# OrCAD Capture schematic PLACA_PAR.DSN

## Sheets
1 PAGE2: size A
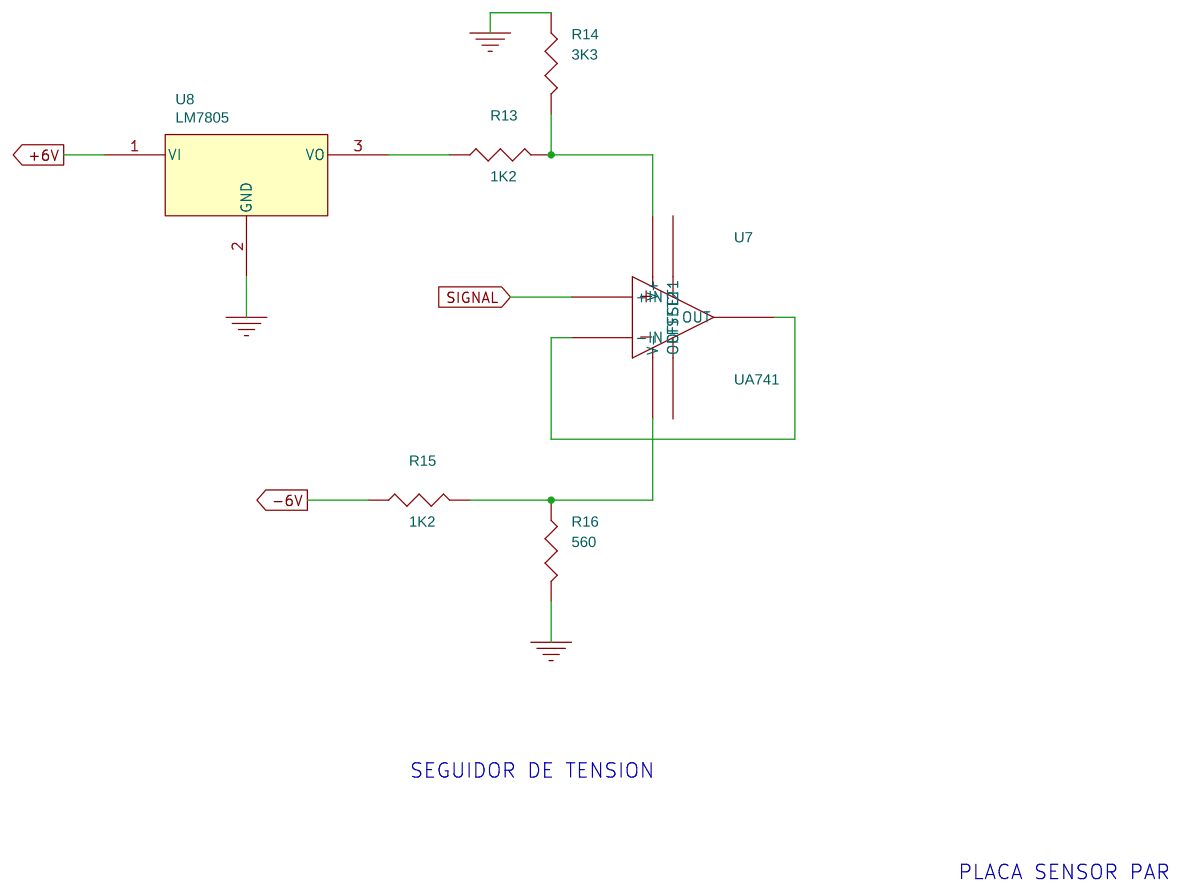
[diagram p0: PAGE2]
2 PAGE1: size A
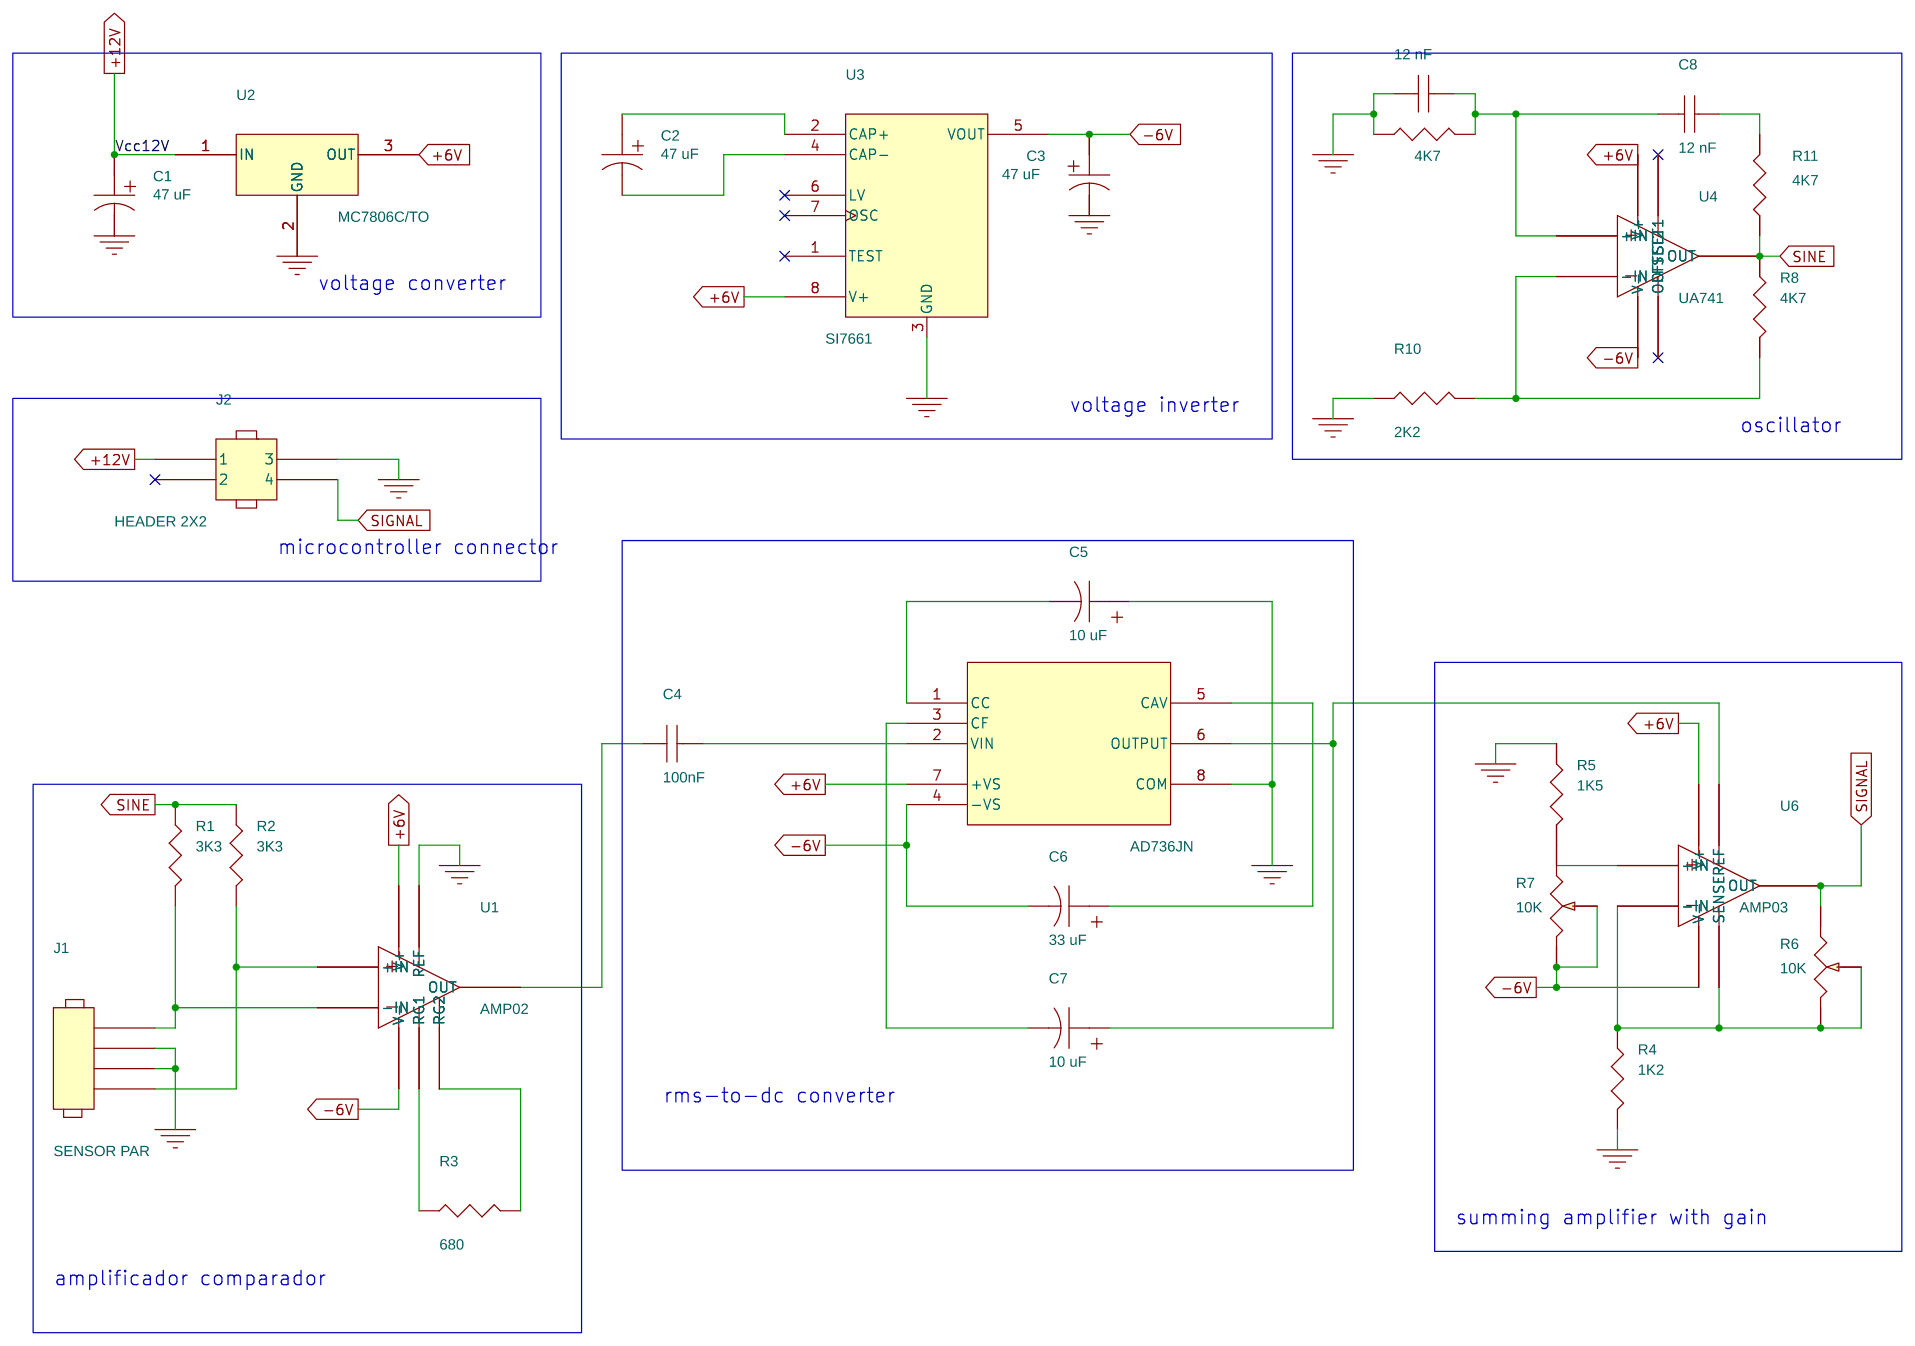
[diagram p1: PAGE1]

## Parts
sheet PAGE1
C1  47 uF
C2  47 uF
C3  47 uF
C4  100nF
C5  10 uF
C6  33 uF
C7  10 uF
C8  12 nF
C9  12 nF
J1  SENSOR PAR
J2  HEADER 2X2
R1  3K3
R2  3K3
R3  680
R4  1K2
R5  1K5
R6  10K
R7  10K
R8  4K7
R10  2K2
R11  4K7
R12  4K7
U1  AMP02
U2  MC7806C/TO
U3  SI7661
U4  UA741
U5  AD736AQ
U6  AMP03
sheet PAGE2
R13  1K2
R14  3K3
R15  1K2
R16  560
U7  UA741
U8  LM7805

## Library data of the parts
C1-C3 C5-C7 = CAPACITOR_POL
C4 C8 C9 = CAPACITOR_NON-POL
J1 = 4_HEADER
J2 = HEADER_2X2
R1-R5 R8 R10-R12 = RESISTOR
R6 R7 = POT
U1 = AMP02
U2 = MC7806C_TO_1
U3 = SI7661_0
U4 U7 = UA741
U5 = AD736AQ: SymName: AD736JN
U6 = AMP03
R13-R16 = R
U8 = LM7805

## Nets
+6V: U1.7(V+) U2.3(OUT) U3.8(V+) U4.7(V+) U5.7(+VS) U6.7(V+) U8.1(VI)
+12V: C1.1 J2.3(1) U2.1(IN)
-6V: C3.1 C6.2 R7.2(WIPER) R7.3(B) R15.1 U1.4(V-) U3.5(VOUT) U4.4(V-) U5.4(-VS) U6.4(V-)
GND_POWER: C1.2 C3.2 C5.1 C9.1 J1.2 J1.3 J2.1(3) R4.2 R5.1 R10.1 R12.1 U1.5(REF) U2.2(GND) U3.3(GND) U5.8(COM)
0: R14.1 R16.2 U8.2(GND)
SIGNAL: J2.2(4) R6.1(A) U6.6(OUT) U7.3(+IN)
SINE: R1.1 R2.1 R8.1 R11.1 U4.6(OUT)
N13200: J1.4 R2.2 U1.3(+IN)
N13224: J1.1 R1.2 U1.2(-IN)
N13330: C2.1 U3.2(CAP+)
N13338: C2.2 U3.4(CAP-)
N13450: R3.1 U1.1(RG1)
N13470: R3.2 U1.8(RG2)
N13646: C5.2 U5.1(CC)
N13658: C6.1 U5.5(CAV)
N13678: C7.2 U5.3(CF)
N13706: C7.1 U5.6(OUTPUT) U6.1(REF)
N13722: C4.1 U1.6(OUT)
N13726: C4.2 U5.2(VIN)
N13800: R4.1 R6.2(WIPER) R6.3(B) U6.2(-IN) U6.5(SENSE)
N13986: R8.2 R10.2 U4.2(-IN)
N14062: C8.2 C9.2 R12.2 U4.3(+IN)
N14465: R5.2 R7.1(A)
N14817: C8.1 R11.2
N15295: U7.2(-IN) U7.6(OUT)
N15564: R13.2 R14.2 U7.7(V+)
N15568: R13.1 U8.3(VO)
N15765: R15.2 R16.1 U7.4(V-)

Not connected (* = marked no-connect by the designer): J2 4(2)*; U3 1(TEST)* 6(LV)* 7(OSC)*; U4 1(OFFSET1)* 5(OFFSET2)*; U6 3(+IN); U7 1(OFFSET1) 5(OFFSET2)

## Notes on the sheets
sheet 1
- SEGUIDOR DE TENSION
- PLACA SENSOR PAR
sheet 2
- voltage converter
- voltage inverter
- oscillator
- microcontroller connector
- rms-to-dc converter
- summing amplifier with gain
- amplificador comparador
